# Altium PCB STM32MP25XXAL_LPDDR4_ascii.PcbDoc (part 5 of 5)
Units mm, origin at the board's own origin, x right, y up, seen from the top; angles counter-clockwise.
Board outline 125 x 95 mm, 6 copper layers (Top Layer, Signal Layer 1, Signal Layer 2, Signal Layer 3, Signal Layer 4, Bottom Layer), stack 1.403 mm thick; 182 components, 297 nets, 1131 pads, 958 vias.
Unrouted connection lines stored in the file: 5.
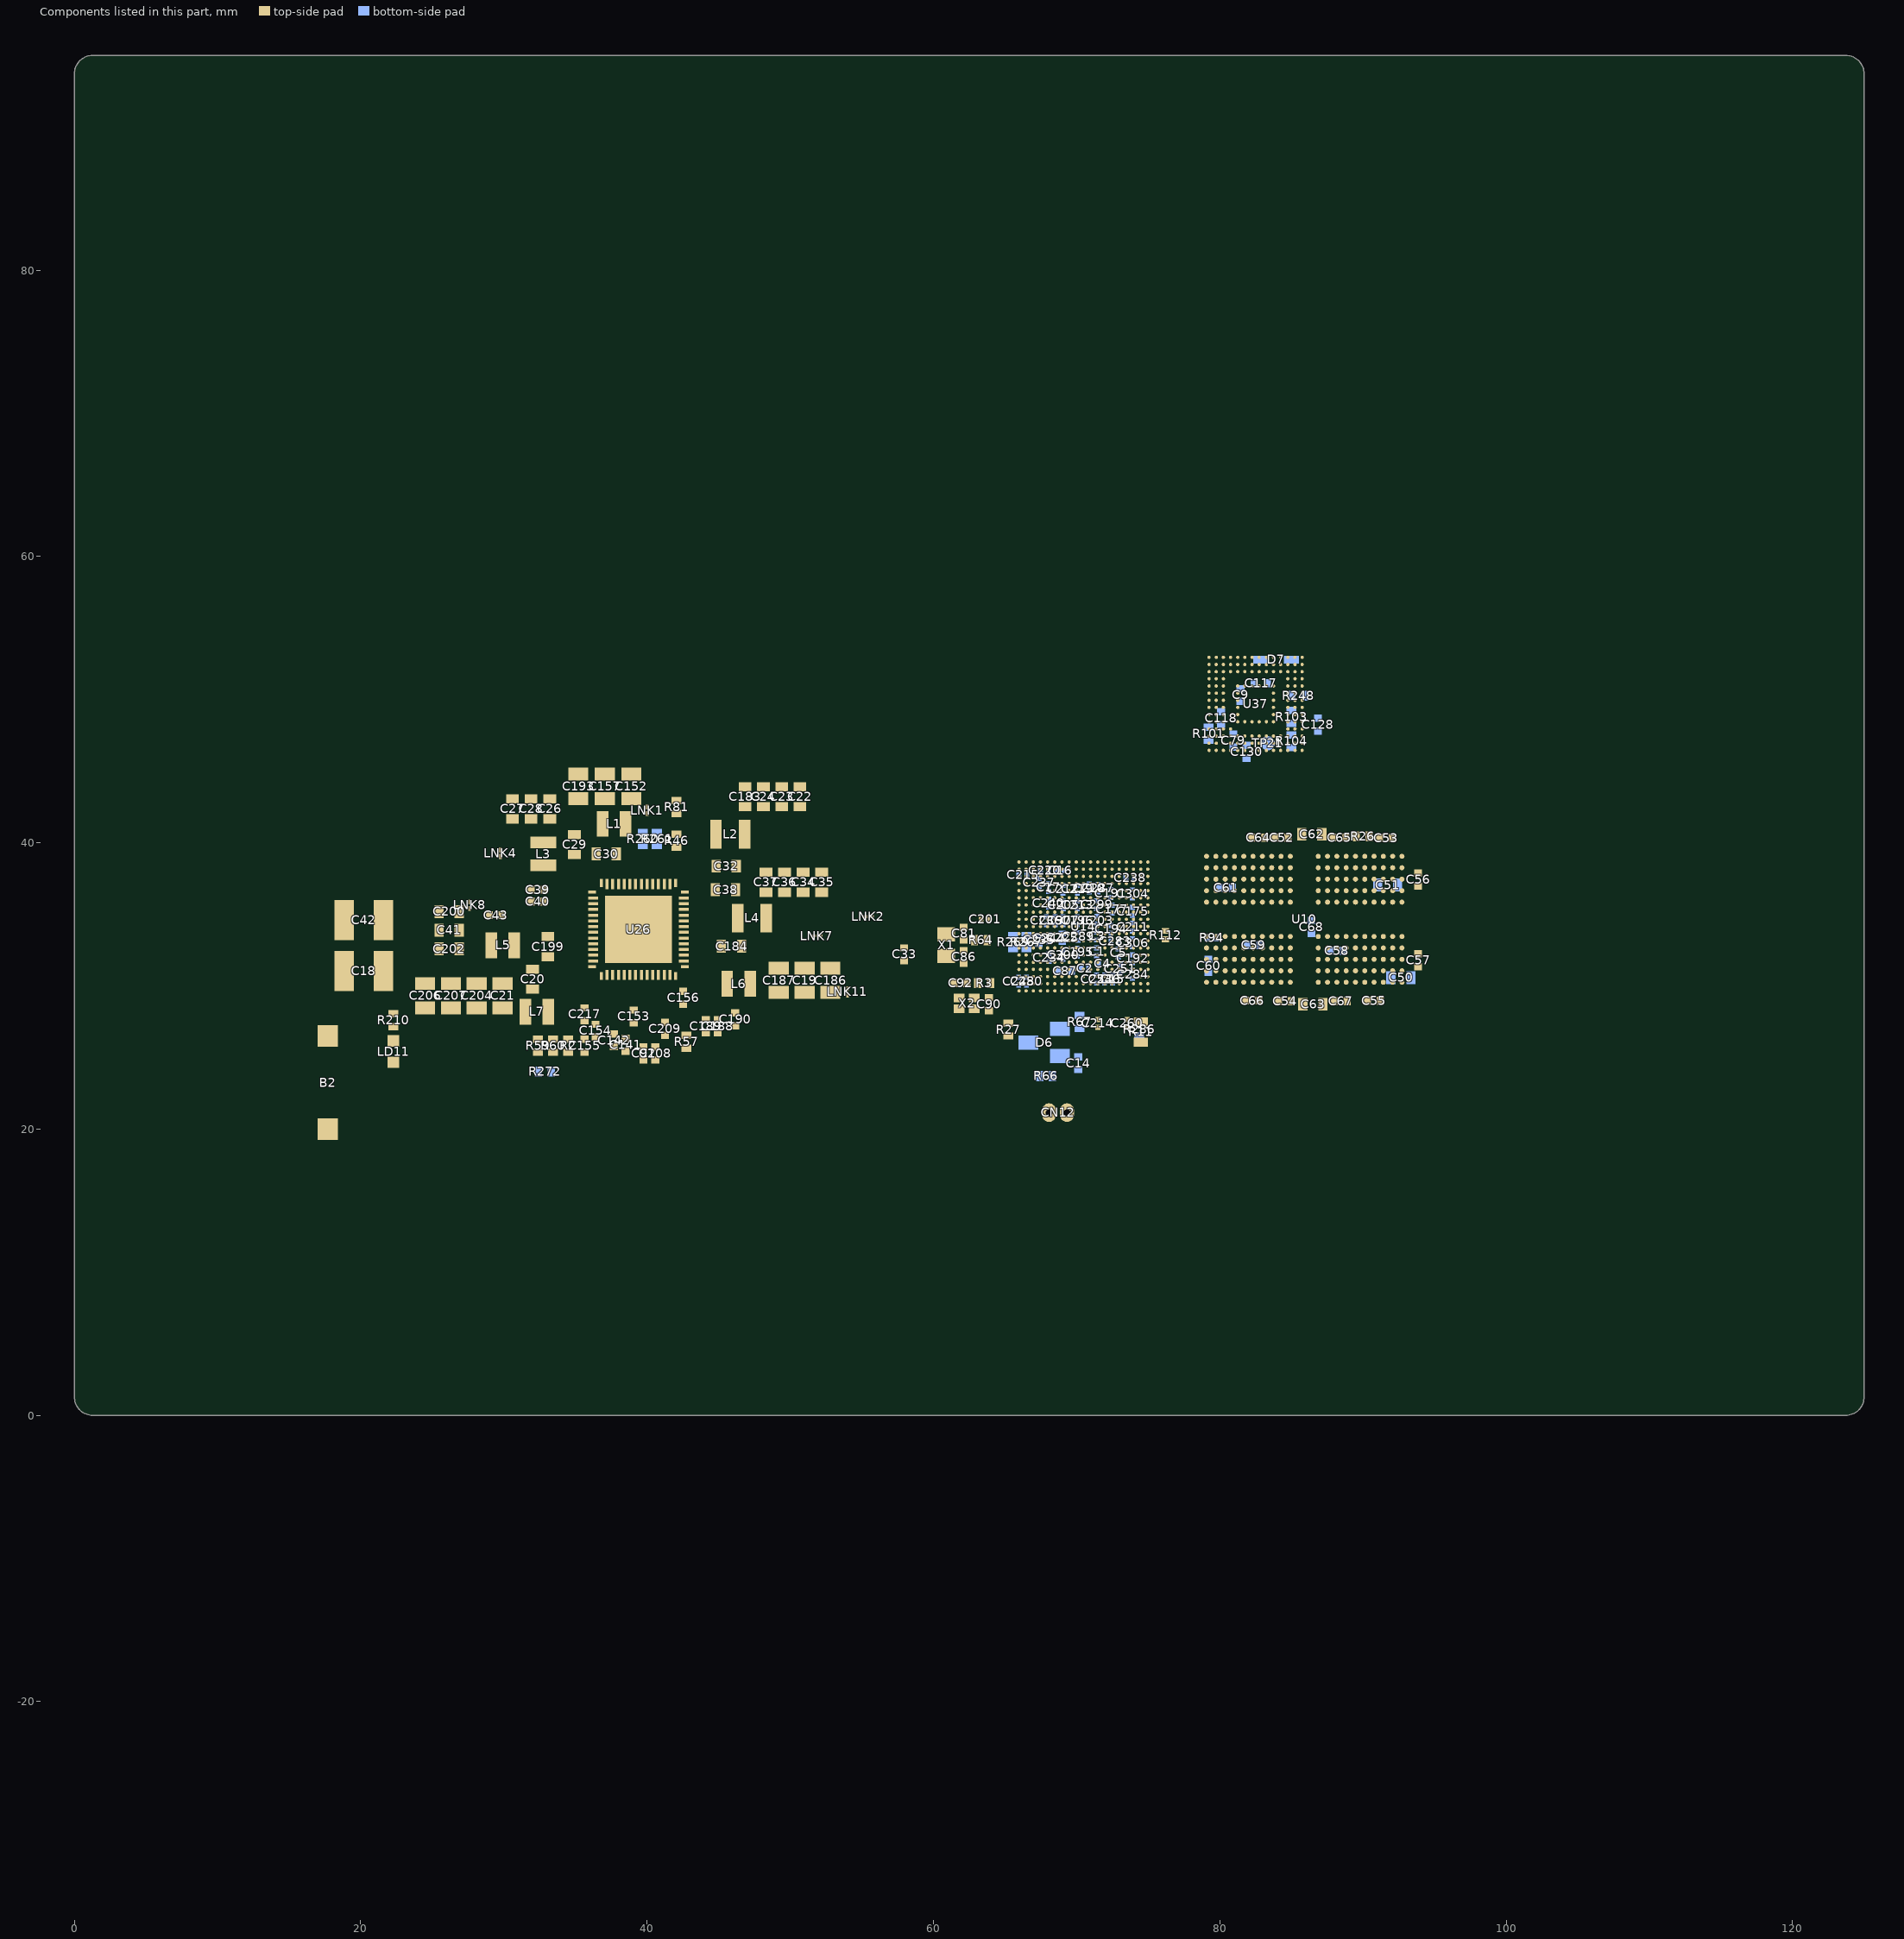
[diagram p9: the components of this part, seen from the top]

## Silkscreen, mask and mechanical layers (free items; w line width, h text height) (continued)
M21-Bottom Sheet Box:
  circle w0.254: c21.598,-32.885 r1.3
  lines w0.254: 21.559,-23.363 22.321,-25.649 ; 21.813,-23.363 22.575,-25.649 ; 21.979,-23.36 22.741,-25.646 ; 22.067,-25.649 21.305,-23.363 38.069,-23.363 cw(c38.309,-26.004) 40.113,-27.948 37.047,-31.485 45.839,-31.485 ; 22.073,-25.649 25.766,-25.649 ; 24.711,-32.261 20.412,-21.484 39.861,-21.484 ; 24.712,-32.264 ccw(c27.261,-31.244) 27.51,-33.978 46.832,-33.978 42.486,-23.083 ; 25.766,-25.395 28.655,-33.774 ; 25.994,-25.404 28.863,-33.724 ; 26.248,-25.404 29.117,-33.724 ; 26.502,-25.404 29.371,-33.724 ; 26.756,-25.404 29.625,-33.724 ; 27.01,-25.404 29.879,-33.724 ; 27.264,-25.404 30.133,-33.724 ; 27.401,-25.649 40.394,-25.649 ; 27.518,-25.404 30.387,-33.724 ; 27.772,-25.404 30.641,-33.724 ; 27.899,-25.404 30.768,-33.724 ; 28.101,-25.395 30.991,-33.774 ; 34.425,-31.615 39.73,-25.494 ; 34.425,-31.234 39.73,-25.113 ; 34.552,-31.996 39.857,-25.875 ; 34.552,-31.742 39.857,-25.621 ; 34.552,-30.853 39.857,-24.732 ; 34.607,-32.187 39.857,-26.129 ; 34.625,-30.425 39.93,-24.304 ; 34.679,-32.377 39.984,-26.256 ; 34.806,-32.504 40.111,-26.383 ; 34.933,-32.631 40.238,-26.51 ; 35.06,-32.758 40.365,-26.637 ; 35.187,-33.139 40.492,-27.018 ; 35.187,-32.885 40.492,-26.764 ; 35.324,-33.274 40.746,-27.018 ; 36.335,-33.886 cw(c37.067,-31.337) 35.264,-29.394 37.628,-26.665 ccw(c37.298,-26.203) 37.272,-25.635 ; 37.956,-30.507 ccw(c38.254,-30.964) 38.359,-31.499 ; 39.863,-21.484 cw(c40.099,-24.086) 42.525,-23.116
  lines w0.3: 28.655,-33.774 30.991,-33.774 ; 48.416,-37.864 48.416,-17.864 ; 48.416,-32.864 108.416,-32.864 ; 48.416,-27.864 108.416,-27.864 ; 48.416,-22.864 108.416,-22.864 ; 68.416,-37.864 68.416,-22.864 ; 18.416,-37.864 18.416,-17.864 108.416,-17.864 108.416,-37.864 18.416,-37.864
